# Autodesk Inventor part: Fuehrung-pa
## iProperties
Created: 2012-11
Part Number: Fuehrung-pa
Document SubType Name: Modeling
Designer: Palme
Density: 1 g/cm^3
Author: Palme
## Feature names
1. Sweeping1
